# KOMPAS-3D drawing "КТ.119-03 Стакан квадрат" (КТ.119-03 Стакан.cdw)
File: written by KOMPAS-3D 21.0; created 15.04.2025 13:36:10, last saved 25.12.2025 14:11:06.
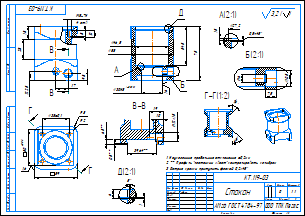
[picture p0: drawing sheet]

Sheet 1: A3, landscape

Document properties: Автор: Марсель; Знак неуказанной шероховатости: 4; Параметр неуказанной шероховатости: 3,2; Полное имя файла: КТ.119-03 Стакан квадрат.m3d; Организация: Марсель

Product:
- Part/product: КТ.119-03 Стакан квадрат
    Комментарий: Марсель

Title block, sheet 1: Наименование: Стакан; designation: КТ.119-03; Материал: АМг6 ГОСТ 4784-97; Масса: 0; Количество листов документа: 1; organisation: ООО ТПК Пегас; Форматы листов документа: A3; stored path: D:\Marat\work\eholot\KazanTarget\детали\детали KT Pro 1\КТ.119-01 Стакан\Стакан _ КТ.119-01.cdw; Разработал: Гайсин

Views: Вид 1, Снизу, Проекционный вид 3, Местный разрез 1, Выносной элемент 4, Выносной элемент 6, Разрез Д-Д, Выносной элемент 9, Проекционный вид 13, Разрез Г-Г, Выносной элемент А, Выносной элемент, Выносной элемент Б, Разрез В-В, Выносной элемент Г
Referenced files in D:\Marat\work\eholot\KazanTarget\детали\детали KT Pro 1\КТ.119-01 Стакан\: КТ.119-01 Стакан.m3d
Referenced files in C:\Users\User\Desktop\Pelorus PRO доработки\ЗАФИКСИРОВАЛИ\Стакан\: КТ.119-03 Стакан квадрат.m3d
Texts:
  КТ.119-03 Стакан квадрат
Dimensions and other numbers on the sheet: 1,6; 59; 8; 2; 50; 38±0,1; 58; 46,5; 30; 75; 54,5; 1,5; 27,2; 0,5; 10,5; 6; 7,5; 10; 12; 6,5; 39,64; 19; 1; 3,2; 1:1; 0

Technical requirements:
  Неуказанные предельные отклонения ±0,2мм.
  ** Профиль "ласточкин хвост" контролировать калибром.
  Острые кромки притупить фаской 0,2х45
